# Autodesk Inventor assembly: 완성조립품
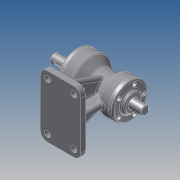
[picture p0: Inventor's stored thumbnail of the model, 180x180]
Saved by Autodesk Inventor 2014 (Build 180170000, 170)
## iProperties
Created: 2015-08
Part Number: 완성조립품
Document SubType Name: Assembly
Designer: user
Author: user
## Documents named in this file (10)
- C:\Users\user\Desktop\450806V1021\완성조립품.iam
- C:\Users\user\Desktop\450806V1021\1-본체.ipt
- C:\Users\user\Desktop\450806V1021\뒤커버.ipt
- C:\Users\user\Desktop\450806V1021\베어링 6203.ipt
- C:\Users\user\Desktop\450806V1021\베어링 6205.ipt
- C:\Users\user\Desktop\450806V1021\앞커버.ipt
- C:\Users\user\Desktop\450806V1021\오일실 .ipt
- 오일실 .ipt
- C:\Users\user\Desktop\450806V1021\축.ipt
- C:\Users\user\Desktop\450806V1021\M4x0.5.ipt
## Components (7 placed, 2 different names)
1. 1-본체:1 — Mate:1, Mate:2, Mate:3, Mate:4, Mate:9, Mate:10, Mate:11, Mate:12, Mate:13, Mate:14
2. M4x0.5:2 — Insert:2
3. M4x0.5:1 — Insert:1
4. M4x0.5:3
5. M4x0.5:4
6. M4x0.5:5
7. M4x0.5:6
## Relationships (12: Mate 10, Insert 2)
- Mate:1: 1-본체:1
- Mate:2: 1-본체:1
- Mate:3: 1-본체:1
- Mate:4: 1-본체:1
- Mate:9: 1-본체:1
- Mate:10: 1-본체:1
- Mate:11: 1-본체:1
- Mate:12: 1-본체:1
- Mate:13: 1-본체:1
- Mate:14: 1-본체:1
- Insert:1: M4x0.5:1
- Insert:2: M4x0.5:2
